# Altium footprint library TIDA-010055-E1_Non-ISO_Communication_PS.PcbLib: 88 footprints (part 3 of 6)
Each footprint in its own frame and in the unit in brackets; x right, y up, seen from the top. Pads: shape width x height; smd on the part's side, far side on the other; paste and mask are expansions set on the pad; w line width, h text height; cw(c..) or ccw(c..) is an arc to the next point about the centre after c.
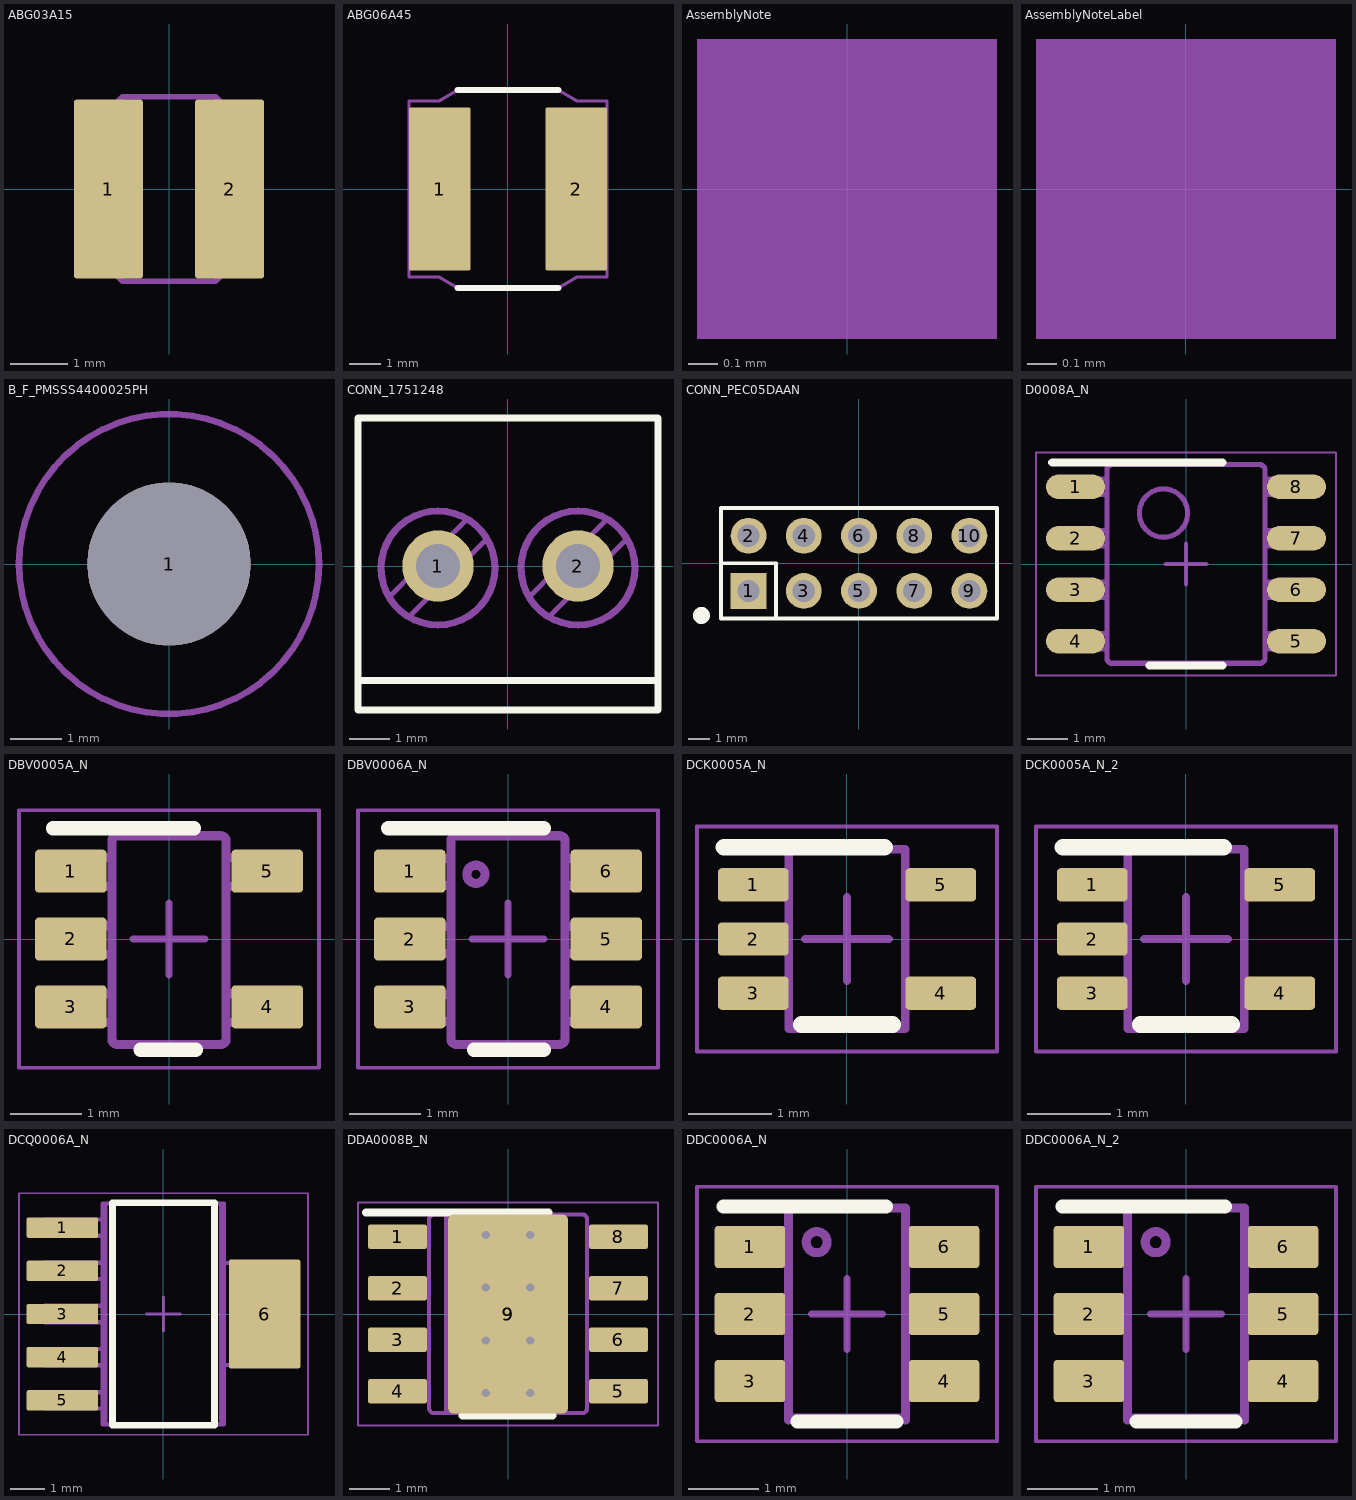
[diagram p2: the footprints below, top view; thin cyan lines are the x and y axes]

## ABG03A15 [mm] "SMD, 2-Leads, Body 3x3mm"
height 1.5
pads (2):
  rrect8% 1.2x3.1 smd: 1(-1.05,0) 2(1.05,0)
Mechanical 5:
  lines w0.1: -1.6,-1.2 -1.6,1.2 -1.2,1.2 -0.8,1.6 0.8,1.6 1.2,1.2 1.6,1.2 1.6,-1.2 1.2,-1.2 0.8,-1.6 -0.8,-1.6 -1.2,-1.2 -1.6,-1.2
  text ".Designator" at -3.1,-0.5 h0.64
3D body: height 1.5, standoff 0, extent -1.601,-1.601 1.601,1.601

## ABG06A45 [mm] "SMD, 2-Leads, Body 6x6mm"
height 4.5
pads (2):
  rrect5% 1.95x5.2 smd: 1(-2.175,0) 2(2.175,0)
Top Overlay:
  lines w0.2: -1.6,-3.15 1.6,-3.15 ; -1.6,3.15 1.6,3.15
Mechanical 5:
  lines w0.1: -3.15,-2.8 -3.15,2.8 -2.2,2.8 -1.6,3.15 1.6,3.15 2.2,2.8 3.15,2.8 3.15,-2.8 2.2,-2.8 1.6,-3.15 -1.6,-3.15 -2.2,-2.8 -3.15,-2.8
  text ".Designator" at -5.231,-0.83 h0.64
3D body: height 4.5, standoff 0, extent -3.151,-3.151 3.151,3.151

## AssemblyNote [mm] "Assembly Note"
Mechanical 5:
  rectangle: -0.508,-0.508 0.508,0.508
  text ".Comment" at 1.143,-0.508 h0.64
  text ".Designator" at -4.191,-0.508 h0.64

## AssemblyNoteLabel [mm] "Assembly Note for PCB Labels"
Mechanical 5:
  rectangle: -0.508,-0.508 0.508,0.508
  text "Install label in silkscreened box after final wash.  Text shall be 8 pt font.  Text shall be per the Label Table in the PDF schematic." at 1.143,-0.508 h0.64
  text ".Designator" at -4.191,-0.508 h0.64

## B_F_PMSSS4400025PH [mm] "MACHINE SCREW PAN PHILLIPS 4-40"
height 2.1
pads (1):
  round 3.175 hole 3.175 unplated: 1(0,0)
Mechanical 5:
  circle w0.127: c0,0 r2.921
  text ".Designator" at -0.52,-0.342 h0.64
3D body "PMSSS 440 0025 PH.stp": height 2.01, standoff -6.3, extent -2.781,-2.781 2.781,2.781

## CONN_1751248 [mm] "Phoenix Contact"
height 8.5
pads (2):
  round 1.778 hole 1.1: 1(-1.75,0) 2(1.75,0)
Top Overlay:
  lines w0.178: -3.75,-2.861 3.75,-2.861 ; -3.75,-2.861 -3.75,-3.3 -3.75,-3.6 3.75,-3.6 3.75,-3.3 3.75,-2.861 ; -3.75,-2.861 -3.75,-2.049 -3.75,-1.566 -3.75,1.487 -3.75,1.962 -3.75,3.7 3.75,3.7 3.75,1.962 3.75,1.487 3.75,-1.566 3.75,-2.049 3.75,-2.861
Mechanical 5:
  lines w0.127: -3.75,-2.861 -3.75,-2.049 -3.75,-1.566 -3.75,1.487 -3.75,1.962 -3.75,3.7 3.75,3.7 3.75,1.962 3.75,1.487 3.75,-1.566 3.75,-2.049 3.75,-2.861 ; -3.75,-2.861 -3.75,-3.3 -3.75,-3.6 3.75,-3.6 3.75,-3.3 3.75,-2.861 ; -3.75,-2.861 3.75,-2.861 ; -2.956,-0.761 ccw(c-1.75,-0.05) -2.461,-1.256 ; -2.956,-0.761 cw(c-1.75,-0.05) -1.75,1.35 cw(c-1.75,-0.05) -1.039,1.156 ; -2.956,-0.761 -2.291,-0.096 -1.75,0.445 -1.653,0.542 -1.039,1.156 ; -2.461,-1.256 ccw(c-1.75,-0.05) -1.75,-1.45 ccw(c-1.75,-0.05) -0.544,0.661 ; -2.461,-1.256 -1.755,-0.55 -1.75,-0.545 -1.2,0.005 -0.544,0.661 ; -1.039,1.156 cw(c-1.75,-0.05) -0.544,0.661 ; 0.544,-0.761 cw(c1.75,-0.05) 1.75,1.35 cw(c1.75,-0.05) 2.461,1.156 ; 0.544,-0.761 ccw(c1.75,-0.05) 1.039,-1.256 ; 0.544,-0.761 1.209,-0.096 1.75,0.445 1.847,0.542 2.461,1.156 ; 1.039,-1.256 ccw(c1.75,-0.05) 1.75,-1.45 ccw(c1.75,-0.05) 2.956,0.661 ; 1.039,-1.256 1.745,-0.55 1.75,-0.545 2.3,0.005 2.956,0.661 ; 2.461,1.156 cw(c1.75,-0.05) 2.956,0.661 ; -1.75,-1.5 cw(c-1.75,-0.05) -1.75,1.4 cw(c-1.75,-0.05) -1.75,-1.5 ; 1.75,-1.5 cw(c1.75,-0.05) 1.75,1.4 cw(c1.75,-0.05) 1.75,-1.5
  text ".Designator" at -0.762,2.134 h0.64
3D body "Phoenix_1751248.stp": height 8.52, standoff -3.48, extent -3.75,-3.6 3.75,3.7

## CONN_PEC05DAAN [mm] "SULLINS"
height 8.382
pads (10):
  rect 1.65x1.65 hole 1.016 mask+0: 1(-5.08,-1.27)
  round 1.65 hole 1.016 mask+0: 2(-5.08,1.27) 3(-2.54,-1.27) 4(-2.54,1.27) 5(0,-1.27) 6(0,1.27) 7(2.54,-1.27) 8(2.54,1.27) 9(5.08,-1.27) 10(5.08,1.27)
Top Overlay:
  circle w0.381: c-7.25,-2.4 r0.203
  lines w0.178: -6.35,0 -3.81,0 -3.81,-2.54 ; -6.35,-2.54 -6.35,2.54 6.35,2.54 6.35,-2.54 -6.35,-2.54
Mechanical 5:
  rectangle: -5.588,-1.777 -4.572,-0.761
  lines w0.076: -6.35,-2.54 -6.35,2.54 6.35,2.54 6.35,-2.54 -6.35,-2.54
  lines w0.127: -6.35,-2.54 6.35,-2.54 6.35,2.54 -6.35,2.54 -6.35,-2.54
  text ".Designator" at 0.964,-0.756 h0.64
3D body: height 2.54, standoff 0, extent -6.349,-2.539 6.349,2.539
3D body: height 8.38, standoff -3.05, extent 4.763,0.953 5.398,1.588
3D body: height 8.38, standoff -3.05, extent 4.763,-1.587 5.398,-0.952
3D body: height 8.38, standoff -3.05, extent 2.223,0.953 2.858,1.588
3D body: height 8.38, standoff -3.05, extent 2.223,-1.587 2.858,-0.952
3D body: height 8.38, standoff -3.05, extent -0.317,0.953 0.318,1.588
3D body: height 8.38, standoff -3.05, extent -0.317,-1.587 0.318,-0.952
3D body: height 8.38, standoff -3.05, extent -2.857,-1.587 -2.222,-0.952
3D body: height 8.38, standoff -3.05, extent -2.857,0.953 -2.222,1.588
3D body: height 8.38, standoff -3.05, extent -5.397,0.953 -4.762,1.588
3D body: height 8.38, standoff -3.05, extent -5.397,-1.587 -4.762,-0.952

## D0008A_N [mm] "SOIC, 8-Leads, Body 4.9x3.9mm, Pitch 1.27mm, IPC Medium Density"
height 1.75
pads (8):
  oval 1.45x0.6 smd: 1(-2.725,1.905) 2(-2.725,0.635) 3(-2.725,-0.635) 4(-2.725,-1.905) 5(2.725,-1.905) 6(2.725,-0.635) 7(2.725,0.635) 8(2.725,1.905)
Top Overlay:
  lines w0.2: -3.3,2.5 0.9,2.5 ; -0.9,-2.5 0.9,-2.5
Mechanical 5:
  lines w0.127: -2.375,-2.095 -1.995,-2.095 -1.952,-2.095 -1.952,-1.715 -1.995,-1.715 -2.375,-1.715 ; -2.375,-2.095 -2.589,-2.095 -3.002,-2.095 -3.002,-1.715 -2.589,-1.715 -2.375,-1.715 ; -2.375,-2.095 -2.375,-1.715 ; -2.375,-0.825 -1.995,-0.825 -1.952,-0.825 -1.952,-0.445 -1.995,-0.445 -2.375,-0.445 ; -2.375,-0.825 -2.589,-0.825 -3.002,-0.825 -3.002,-0.445 -2.589,-0.445 -2.375,-0.445 ; -2.375,-0.825 -2.375,-0.445 ; -2.375,0.445 -1.995,0.445 -1.952,0.445 -1.952,0.825 -1.995,0.825 -2.375,0.825 ; -2.375,0.445 -2.589,0.445 -3.002,0.445 -3.002,0.825 -2.589,0.825 -2.375,0.825 ; -2.375,0.445 -2.375,0.825 ; -2.375,1.715 -1.995,1.715 -1.952,1.715 -1.952,2.095 -1.995,2.095 -2.375,2.095 ; -2.375,1.715 -2.589,1.715 -3.002,1.715 -3.002,2.095 -2.589,2.095 -2.375,2.095 ; -2.375,1.715 -2.375,2.095 ; -0.332,-2.45 -1.825,-2.45 -1.826,-2.45 cw(c-1.825,-2.323) -1.952,-2.324 -1.952,-2.323 -1.952,2.323 -1.952,2.324 cw(c-1.825,2.323) -1.826,2.45 -1.825,2.45 -0.332,2.45 ; -0.332,-2.45 -0.182,-2.45 ; -0.332,-2.45 -0.182,-2.45 ; -0.332,2.45 -0.182,2.45 ; -0.332,2.45 -0.182,2.45 ; -0.182,-2.45 0.178,-2.45 ; -0.182,2.45 0.178,2.45 ; 0.178,-2.45 0.328,-2.45 ; 0.178,-2.45 0.328,-2.45 ; 0.178,2.45 0.328,2.45 ; 0.178,2.45 0.328,2.45 ; 0.328,-2.45 1.821,-2.45 1.822,-2.45 ccw(c1.821,-2.323) 1.948,-2.324 1.948,-2.323 1.948,2.323 1.948,2.324 ccw(c1.821,2.323) 1.822,2.45 1.821,2.45 0.328,2.45 ; 2.371,-2.095 2.585,-2.095 2.998,-2.095 2.998,-1.715 2.585,-1.715 2.371,-1.715 ; 2.371,-2.095 1.991,-2.095 1.948,-2.095 1.948,-1.715 1.991,-1.715 2.371,-1.715 ; 2.371,-2.095 2.371,-1.715 ; 2.371,-0.825 2.585,-0.825 2.998,-0.825 2.998,-0.445 2.585,-0.445 2.371,-0.445 ; 2.371,-0.825 1.991,-0.825 1.948,-0.825 1.948,-0.445 1.991,-0.445 2.371,-0.445 ; 2.371,-0.825 2.371,-0.445 ; 2.371,0.445 2.585,0.445 2.998,0.445 2.998,0.825 2.585,0.825 2.371,0.825 ; 2.371,0.445 1.991,0.445 1.948,0.445 1.948,0.825 1.991,0.825 2.371,0.825 ; 2.371,0.445 2.371,0.825 ; 2.371,1.715 2.585,1.715 2.998,1.715 2.998,2.095 2.585,2.095 2.371,2.095 ; 2.371,1.715 1.991,1.715 1.948,1.715 1.948,2.095 1.991,2.095 2.371,2.095 ; 2.371,1.715 2.371,2.095 ; -0.555,0.659 cw(c-0.555,1.256) -0.555,1.853 cw(c-0.555,1.256) -0.555,0.659
  text ".Designator" at -0.85,-0.645 h0.64
Mechanical 15:
  lines w0.05: -3.7,-2.75 3.7,-2.75 3.7,2.75 -3.7,2.75 -3.7,-2.75
  lines w0.1: -0.5,0 0.5,0 ; 0,-0.5 0,0.5
3D body "D0008A.stp": height 1.63, standoff 0, extent -3,-2.45 3,2.45

## DBV0005A_N [mm] "SOT23, 5-Leads, Body 2.9x1.6mm, Pitch 0.95mm, Lead Span 2.8mm, IPC Medium Density"
height 1.45
pads (5):
  rrect17% 1x0.6 smd: 1(-1.375,0.95) 2(-1.375,0) 3(-1.375,-0.95) 4(1.375,-0.95) 5(1.375,0.95)
Top Overlay:
  lines w0.2: -1.625,1.55 0.35,1.55 ; -0.4,-1.55 0.375,-1.55
Mechanical 5:
  lines w0.127: -0.801,1.371 cw(c-0.725,1.37) -0.725,1.446 ; -0.801,1.37 -0.801,-1.399 -0.801,-1.4 ccw(c-0.725,-1.399) -0.725,-1.475 ; -0.801,1.37 -0.801,1.371 ; -0.725,-1.475 -0.725,-1.475 ; -0.725,-1.475 0.723,-1.475 0.724,-1.475 ccw(c0.723,-1.399) 0.799,-1.4 0.799,-1.399 0.799,1.37 ; -0.725,1.446 0.723,1.446 0.724,1.446 cw(c0.723,1.37) 0.799,1.371 ; -0.725,1.446 -0.725,1.446 ; 0.799,1.37 0.799,1.371 ; -1.423,-1.167 -1.199,-1.167 -1.105,-1.167 -1.088,-1.167 -0.835,-1.167 -0.801,-1.167 -0.801,-0.767 -0.835,-0.767 -1.088,-0.767 -1.105,-0.767 -1.199,-0.767 -1.423,-0.767 -1.423,-1.167 ; -1.423,-0.215 -1.199,-0.215 -1.105,-0.215 -1.088,-0.215 -0.835,-0.215 -0.801,-0.215 -0.801,0.186 -0.835,0.186 -1.088,0.186 -1.105,0.186 -1.199,0.186 -1.423,0.186 -1.423,-0.215 ; -1.423,0.738 -1.199,0.738 -1.105,0.738 -1.088,0.738 -0.835,0.738 -0.801,0.738 -0.801,1.138 -0.835,1.138 -1.088,1.138 -1.105,1.138 -1.199,1.138 -1.423,1.138 -1.423,0.738 ; 0.799,-1.167 0.799,-0.767 0.834,-0.767 1.087,-0.767 1.103,-0.767 1.198,-0.767 1.422,-0.767 1.422,-1.167 1.198,-1.167 1.103,-1.167 1.087,-1.167 0.834,-1.167 0.799,-1.167 ; 0.799,0.738 0.799,1.138 0.834,1.138 1.087,1.138 1.103,1.138 1.198,1.138 1.422,1.138 1.422,0.738 1.198,0.738 1.103,0.738 1.087,0.738 0.834,0.738 0.799,0.738
  text ".Designator" at -0.254,0.787 h0.64
Mechanical 15:
  lines w0.05: -2.1,-1.8 2.1,-1.8 2.1,1.8 -2.1,1.8 -2.1,-1.8
  lines w0.1: -0.5,0 0.5,0 ; 0,-0.5 0,0.5
3D body "DBV0005A.stp": height 1.09, standoff 0, extent -1.422,-1.461 1.423,1.46

## DBV0006A_N [mm] "SOT23, 6-Leads, Body 2.9x1.6mm, Pitch 0.95mm, Lead Span 2.8mm, IPC Medium Density"
height 1.45
pads (6):
  rrect17% 1x0.6 smd: 1(-1.375,0.95) 2(-1.375,0) 3(-1.375,-0.95) 4(1.375,-0.95) 5(1.375,0) 6(1.375,0.95)
Top Overlay:
  lines w0.2: -1.675,1.55 0.5,1.55 ; -0.475,-1.55 0.5,-1.55
Mechanical 5:
  lines w0.127: 0.724,-1.475 ccw(c0.723,-1.399) 0.8,-1.399 0.8,1.37 ccw(c0.723,1.37) 0.724,1.446 ; 0.723,-1.475 0.724,-1.475 ; 0.723,-1.475 -0.724,-1.475 -0.725,-1.475 cw(c-0.724,-1.399) -0.801,-1.399 -0.801,1.37 cw(c-0.724,1.37) -0.725,1.446 -0.724,1.446 0.723,1.446 ; 0.723,1.446 0.724,1.446 ; -1.423,-1.154 -1.206,-1.154 -1.113,-1.154 -1.081,-1.154 -0.828,-1.154 -0.801,-1.154 -0.801,-0.78 -0.828,-0.78 -1.081,-0.78 -1.113,-0.78 -1.206,-0.78 -1.423,-0.78 -1.423,-1.154 ; -1.423,-0.202 -1.206,-0.202 -1.113,-0.202 -1.081,-0.202 -0.828,-0.202 -0.801,-0.202 -0.801,0.173 -0.828,0.173 -1.081,0.173 -1.113,0.173 -1.206,0.173 -1.423,0.173 -1.423,-0.202 ; -1.423,0.751 -1.206,0.751 -1.113,0.751 -1.081,0.751 -0.828,0.751 -0.801,0.751 -0.801,1.125 -0.828,1.125 -1.081,1.125 -1.113,1.125 -1.206,1.125 -1.423,1.125 -1.423,0.751 ; -0.577,0.906 cw(c-0.45,0.906) -0.323,0.906 cw(c-0.45,0.906) -0.577,0.906 ; 0.8,-1.154 0.827,-1.154 1.08,-1.154 1.112,-1.154 1.205,-1.154 1.422,-1.154 1.422,-0.78 1.205,-0.78 1.112,-0.78 1.08,-0.78 0.827,-0.78 0.8,-0.78 0.8,-1.154 ; 0.8,-0.202 0.827,-0.202 1.08,-0.202 1.112,-0.202 1.205,-0.202 1.422,-0.202 1.422,0.173 1.205,0.173 1.112,0.173 1.08,0.173 0.827,0.173 0.8,0.173 0.8,-0.202 ; 0.8,0.751 0.827,0.751 1.08,0.751 1.112,0.751 1.205,0.751 1.422,0.751 1.422,1.125 1.205,1.125 1.112,1.125 1.08,1.125 0.827,1.125 0.8,1.125 0.8,0.751
  text ".Designator" at -0.249,0.074 h0.64
Mechanical 15:
  lines w0.05: -2.1,-1.8 2.1,-1.8 2.1,1.8 -2.1,1.8 -2.1,-1.8
  lines w0.1: -0.5,0 0.5,0 ; 0,-0.5 0,0.5
3D body "DBV0006A.stp": height 1.12, standoff 0, extent -1.422,-1.461 1.423,1.46

## DCK0005A_N [mm] "SOT353, 5-Leads, Body 2x1.3mm, Pitch 0.65mm, Lead Span 2.1mm, IPC Medium Density"
height 1.1
pads (5):
  rrect25% 0.85x0.4 smd: 1(-1.125,0.65) 2(-1.125,0) 3(-1.125,-0.65) 4(1.125,-0.65) 5(1.125,0.65)
Top Overlay:
  lines w0.2: -1.475,1.1 0.45,1.1 ; -0.55,-1.025 0.55,-1.025
Mechanical 5:
  lines w0.1: -0.7,-1.075 0.7,-1.075 0.7,1.075 -0.7,1.075 -0.7,-1.075
  lines w0.127: -0.865,0.762 -0.853,0.762 ; -0.711,-0.763 -0.853,-0.763 -0.865,-0.763 -0.959,-0.763 -1.143,-0.763 -1.143,-0.538 -0.959,-0.538 -0.865,-0.538 -0.853,-0.538 -0.711,-0.538 ; -0.711,-0.113 -0.853,-0.113 -0.865,-0.113 -0.959,-0.113 -1.143,-0.113 -1.143,0.112 -0.959,0.112 -0.865,0.112 -0.853,0.112 -0.711,0.112 ; -0.711,0.537 -0.853,0.537 -0.865,0.537 -0.959,0.537 -1.143,0.537 -1.143,0.762 -0.959,0.762 -0.711,0.762 ; 0.711,-0.763 0.847,-0.763 0.859,-0.763 0.953,-0.763 1.137,-0.763 1.137,-0.538 0.953,-0.538 0.859,-0.538 0.847,-0.538 0.711,-0.538 ; 0.711,0.537 0.847,0.537 0.859,0.537 0.953,0.537 1.137,0.537 1.137,0.762 0.953,0.762 0.859,0.762 0.847,0.762 0.711,0.762
  text ".Designator" at -0.254,0.838 h0.64
Mechanical 15:
  lines w0.05: -1.8,-1.35 1.8,-1.35 1.8,1.35 -1.8,1.35 -1.8,-1.35
  lines w0.1: -0.5,0 0.5,0 ; 0,-0.5 0,0.5
3D body "DCK0005A.stp": height 0.95, standoff 0, extent -1.14,-1 1.14,1

## DCK0005A_N_2 [mm]
pads (5):
  rrect25% 0.85x0.4 smd: 1(-1.125,0.65) 2(-1.125,0) 3(-1.125,-0.65) 4(1.125,-0.65) 5(1.125,0.65)
Top Overlay:
  lines w0.2: -1.475,1.1 0.45,1.1 ; -0.55,-1.025 0.55,-1.025
Mechanical 5:
  lines w0.1: -0.7,-1.075 0.7,-1.075 0.7,1.075 -0.7,1.075 -0.7,-1.075
  lines w0.127: -0.865,0.762 -0.853,0.762 ; -0.711,-0.763 -0.853,-0.763 -0.865,-0.763 -0.959,-0.763 -1.143,-0.763 -1.143,-0.538 -0.959,-0.538 -0.865,-0.538 -0.853,-0.538 -0.711,-0.538 ; -0.711,-0.113 -0.853,-0.113 -0.865,-0.113 -0.959,-0.113 -1.143,-0.113 -1.143,0.112 -0.959,0.112 -0.865,0.112 -0.853,0.112 -0.711,0.112 ; -0.711,0.537 -0.853,0.537 -0.865,0.537 -0.959,0.537 -1.143,0.537 -1.143,0.762 -0.959,0.762 -0.711,0.762 ; 0.711,-0.763 0.847,-0.763 0.859,-0.763 0.953,-0.763 1.137,-0.763 1.137,-0.538 0.953,-0.538 0.859,-0.538 0.847,-0.538 0.711,-0.538 ; 0.711,0.537 0.847,0.537 0.859,0.537 0.953,0.537 1.137,0.537 1.137,0.762 0.953,0.762 0.859,0.762 0.847,0.762 0.711,0.762
  text ".Designator" at 0.254,-0.787 h0.64
Mechanical 15:
  lines w0.05: -1.8,-1.35 1.8,-1.35 1.8,1.35 -1.8,1.35 -1.8,-1.35
  lines w0.1: -0.5,0 0.5,0 ; 0,-0.5 0,0.5
3D body "DCK0005A.stp": height 0.95, standoff 0, extent -1.14,-1 1.14,1

## DCQ0006A_N [mm] "SOT223, 6-Leads, Body 6.6x7.3mm (max), Pitch 1.27mm, IPC Medium Density"
height 1.8
pads (6):
  rrect17% 2.1x0.6 smd: 1(-2.975,2.54) 2(-2.975,1.27) 3(-2.975,0) 4(-2.975,-1.27) 5(-2.975,-2.54)
  rrect5% 2.1x3.2 smd: 6(2.975,0)
Top Overlay:
  lines w0.2: -1.5,-3.275 1.5,-3.275 1.5,3.275 -1.5,3.275 -1.5,-3.275
Mechanical 5:
  lines w0.127: -1.713,-3.178 -1.785,-3.25 ; -1.713,3.178 -1.785,3.25 ; -1.707,-3.102 -1.707,3.102 ; 1.697,-3.102 1.697,3.102 ; 1.703,-3.178 1.775,-3.25 ; 1.703,3.178 1.775,3.25 ; -1.785,-3.25 1.775,-3.25 ; -1.785,-3.25 -1.785,3.25 ; -1.785,3.25 1.775,3.25 ; 1.775,-3.25 1.775,3.25 ; -3.485,-2.781 -3.485,-2.299 -2.951,-2.299 -2.834,-2.299 -2.758,-2.299 -2.364,-2.299 -1.785,-2.299 -1.785,-2.781 -2.364,-2.781 -2.758,-2.781 -2.834,-2.781 -2.951,-2.781 -3.485,-2.781 ; -3.485,-1.511 -3.485,-1.029 -2.951,-1.029 -2.834,-1.029 -2.758,-1.029 -2.364,-1.029 -1.785,-1.029 -1.785,-1.511 -2.364,-1.511 -2.758,-1.511 -2.834,-1.511 -2.951,-1.511 -3.485,-1.511 ; -3.485,-0.241 -3.485,0.241 -2.951,0.241 -2.834,0.241 -2.758,0.241 -2.364,0.241 -1.785,0.241 -1.785,-0.241 -2.364,-0.241 -2.758,-0.241 -2.834,-0.241 -2.951,-0.241 -3.485,-0.241 ; -3.485,1.029 -3.485,1.511 -2.951,1.511 -2.834,1.511 -2.758,1.511 -2.364,1.511 -1.785,1.511 -1.785,1.029 -2.364,1.029 -2.758,1.029 -2.834,1.029 -2.951,1.029 -3.485,1.029 ; -3.485,2.299 -3.485,2.781 -2.951,2.781 -2.834,2.781 -2.758,2.781 -2.364,2.781 -1.785,2.781 -1.785,2.299 -2.364,2.299 -2.758,2.299 -2.834,2.299 -2.951,2.299 -3.485,2.299 ; 1.775,-1.5 1.775,1.5 2.354,1.5 2.748,1.5 2.824,1.5 2.941,1.5 3.475,1.5 3.475,-1.5 2.941,-1.5 2.824,-1.5 2.748,-1.5 2.354,-1.5 1.775,-1.5
  text ".Designator" at 0.52,0.513 h0.64
Mechanical 15:
  lines w0.05: -4.25,-3.55 -4.25,3.55 4.25,3.55 4.25,-3.55 -4.25,-3.55
  lines w0.1: -0.5,0 0.5,0 ; 0,-0.5 0,0.5
3D body "DCQ0006A.stp": height 1.8, standoff 0, extent -3.542,-3.25 3.542,3.25

## DDA0008B_N [mm] "SOIC, 8-Leads, Body 4.9x3.9mm, Pitch 1.27mm, Exposed Pad, IPC Medium Density"
height 1.68
pads (11):
  rrect17% 1.45x0.6 smd: 1(-2.725,1.905) 2(-2.725,0.635) 3(-2.725,-0.635) 4(-2.725,-1.905) 5(2.725,-1.905) 6(2.725,-0.635) 7(2.725,0.635) 8(2.725,1.905)
  rrect7% 2.95x4.9 smd paste-1.5 mask-1.5: 9(0,0)
  rrect50% 2.71x3.4 on Top Paste: 9(0,0)
  rrect50% 2.71x3.4 on Top Solder: 9(0,0)
via -0.55,0.65 diameter 0.5 hole 0.2
via 0.55,0.65 diameter 0.5 hole 0.2
via -0.55,-0.65 diameter 0.5 hole 0.2
via 0.55,-0.65 diameter 0.5 hole 0.2
via 0.55,1.95 diameter 0.5 hole 0.2
via -0.55,1.95 diameter 0.5 hole 0.2
via -0.55,-1.95 diameter 0.5 hole 0.2
via 0.55,-1.95 diameter 0.5 hole 0.2
Top Overlay:
  lines w0.2: -3.5,2.5 1,2.5 ; -1.125,-2.5 1.1,-2.5
Mechanical 5:
  lines w0.1: -1.946,-2.321 ccw(c-1.819,-2.32) -1.82,-2.447 ; -1.946,-2.321 -1.946,-2.32 -1.946,2.329 ; -1.946,2.33 -1.946,2.329 ; -1.524,-2.447 -1.524,2.456 ; -1.946,2.33 cw(c-1.819,2.329) -1.82,2.456 ; -1.819,-2.447 1.826,-2.447 1.827,-2.447 ccw(c1.826,-2.32) 1.953,-2.321 1.953,-2.32 1.953,2.329 ; -1.82,-2.447 -1.819,-2.447 ; -1.82,2.456 -1.819,2.456 ; -1.819,2.456 1.826,2.456 1.827,2.456 cw(c1.826,2.329) 1.953,2.33 ; 1.953,2.329 1.953,2.33 ; -2.975,-2.091 -2.975,-1.71 -2.614,-1.71 -2.497,-1.71 -2.473,-1.71 -2.144,-1.71 -1.946,-1.71 -1.946,-2.091 -2.144,-2.091 -2.473,-2.091 -2.497,-2.091 -2.614,-2.091 -2.975,-2.091 ; -2.975,-0.821 -2.975,-0.44 -2.614,-0.44 -2.497,-0.44 -2.473,-0.44 -2.144,-0.44 -1.946,-0.44 -1.946,-0.821 -2.144,-0.821 -2.473,-0.821 -2.497,-0.821 -2.614,-0.821 -2.975,-0.821 ; -2.975,0.449 -2.975,0.83 -2.614,0.83 -2.497,0.83 -2.473,0.83 -2.144,0.83 -1.946,0.83 -1.946,0.449 -2.144,0.449 -2.473,0.449 -2.497,0.449 -2.614,0.449 -2.975,0.449 ; -2.975,1.719 -2.975,2.1 -2.614,2.1 -2.497,2.1 -2.473,2.1 -2.144,2.1 -1.946,2.1 -1.946,1.719 -2.144,1.719 -2.473,1.719 -2.497,1.719 -2.614,1.719 -2.975,1.719 ; -0.632,1.16 ccw(c-0.632,1.478) -0.632,1.795 ccw(c-0.632,1.478) -0.632,1.16 ; 1.953,-2.091 1.953,-1.71 2.15,-1.71 2.479,-1.71 2.503,-1.71 2.621,-1.71 2.981,-1.71 2.981,-2.091 2.621,-2.091 2.503,-2.091 2.479,-2.091 2.15,-2.091 1.953,-2.091 ; 1.953,-0.821 1.953,-0.44 2.15,-0.44 2.479,-0.44 2.503,-0.44 2.621,-0.44 2.981,-0.44 2.981,-0.821 2.621,-0.821 2.503,-0.821 2.479,-0.821 2.15,-0.821 1.953,-0.821 ; 1.953,0.449 1.953,0.83 2.15,0.83 2.479,0.83 2.503,0.83 2.621,0.83 2.981,0.83 2.981,0.449 2.621,0.449 2.503,0.449 2.479,0.449 2.15,0.449 1.953,0.449 ; 1.953,1.719 1.953,2.1 2.15,2.1 2.479,2.1 2.503,2.1 2.621,2.1 2.981,2.1 2.981,1.719 2.621,1.719 2.503,1.719 2.479,1.719 2.15,1.719 1.953,1.719
  text ".Designator" at 0.584,0.182 h0.64
Mechanical 15:
  lines w0.05: -3.7,-2.75 -3.7,2.75 3.7,2.75 3.7,-2.75 -3.7,-2.75
  lines w0.1: -0.5,0 0.5,0 ; 0,-0.5 0,0.5
3D body "DDA0008B.stp": height 1.57, standoff 0, extent -3.014,-2.45 3.014,2.45

## DDC0006A_N [mm]
height 1.1
pads (6):
  rrect17% 1x0.6 smd: 1(-1.375,0.95) 2(-1.375,0) 3(-1.375,-0.95) 4(1.375,-0.95) 5(1.375,0) 6(1.375,0.95)
Top Overlay:
  lines w0.2: -1.75,1.525 0.55,1.525 ; -0.7,-1.524 0.7,-1.524
Mechanical 5:
  lines w0.127: -0.828,-1.5 -0.828,1.5 0.828,1.5 0.828,-1.5 ; -0.825,-1.165 -1.437,-1.165 -1.437,-0.735 -0.825,-0.735 ; -0.825,-0.215 -1.437,-0.215 -1.437,0.215 -0.825,0.215 ; -0.825,0.735 -1.437,0.735 -1.437,1.165 -0.825,1.165 ; -0.754,-1.47 -0.75,-1.47 0.743,-1.47 0.747,-1.47 ; -0.754,1.5 -0.75,1.5 ; 0.743,1.5 0.747,1.5 ; 0.825,-1.165 1.437,-1.165 1.437,-0.735 0.825,-0.735 ; 0.825,-0.215 1.437,-0.215 1.437,0.215 0.825,0.215 ; 0.825,0.735 1.437,0.735 1.437,1.165 0.825,1.165 ; -0.578,1.018 cw(c-0.43,1.018) -0.281,1.018 cw(c-0.43,1.018) -0.578,1.018
  text ".Designator" at 0.67,-3.58 h0.64
Mechanical 15:
  lines w0.05: -2.125,-1.8 2.125,-1.8 2.125,1.8 -2.125,1.8 -2.125,-1.8
  lines w0.1: -0.5,0 0.5,0 ; 0,-0.5 0,0.5
3D body "DDC0006A.stp": height 0.92, standoff 0, extent -1.434,-1.485 1.434,1.485

## DDC0006A_N_2 [mm]
pads (6):
  rrect17% 1x0.6 smd: 1(-1.375,0.95) 2(-1.375,0) 3(-1.375,-0.95) 4(1.375,-0.95) 5(1.375,0) 6(1.375,0.95)
Top Overlay:
  lines w0.2: -1.75,1.525 0.55,1.525 ; -0.7,-1.524 0.7,-1.524
Mechanical 5:
  lines w0.127: -0.828,-1.5 -0.828,1.5 0.828,1.5 0.828,-1.5 ; -0.825,-1.165 -1.437,-1.165 -1.437,-0.735 -0.825,-0.735 ; -0.825,-0.215 -1.437,-0.215 -1.437,0.215 -0.825,0.215 ; -0.825,0.735 -1.437,0.735 -1.437,1.165 -0.825,1.165 ; -0.754,-1.47 -0.75,-1.47 0.743,-1.47 0.747,-1.47 ; -0.754,1.5 -0.75,1.5 ; 0.743,1.5 0.747,1.5 ; 0.825,-1.165 1.437,-1.165 1.437,-0.735 0.825,-0.735 ; 0.825,-0.215 1.437,-0.215 1.437,0.215 0.825,0.215 ; 0.825,0.735 1.437,0.735 1.437,1.165 0.825,1.165 ; -0.578,1.018 cw(c-0.43,1.018) -0.281,1.018 cw(c-0.43,1.018) -0.578,1.018
  text ".Designator" at -0.505,3.086 h0.64
Mechanical 15:
  lines w0.05: -2.125,-1.8 2.125,-1.8 2.125,1.8 -2.125,1.8 -2.125,-1.8
  lines w0.1: -0.5,0 0.5,0 ; 0,-0.5 0,0.5
3D body "DDC0006A.stp": height 0.92, standoff 0, extent -1.434,-1.485 1.434,1.485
